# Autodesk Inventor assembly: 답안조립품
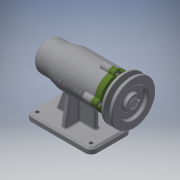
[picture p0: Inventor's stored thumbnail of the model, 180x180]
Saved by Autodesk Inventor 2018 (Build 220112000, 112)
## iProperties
Created: 2019-07
Part Number: 답안조립품
Material: 일반
Document SubType Name: Assembly
Designer: USER
Author: USER
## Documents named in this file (12)
- C:\Users\USER\Desktop\490704V1049\답안조립품.iam
- C:\Users\USER\Desktop\490704V1049\본체.ipt
- C:\Users\USER\Desktop\490704V1049\V벨트풀리.ipt
- C:\Users\USER\Desktop\490704V1049\멈춤나사 M3.ipt
- C:\Users\USER\Desktop\490704V1049\베어링 6004.ipt
- C:\Users\USER\Desktop\490704V1049\베어링 51202.ipt
- C:\Users\USER\Desktop\490704V1049\볼트 M4.ipt
- C:\Users\USER\Desktop\490704V1049\어댑터슬리브.ipt
- C:\Users\USER\Desktop\490704V1049\오일 실.ipt
- C:\Users\USER\Desktop\490704V1049\축.ipt
- C:\Users\USER\Desktop\490704V1049\커버.ipt
- C:\Users\USER\Desktop\490704V1049\키 5 x 5 x 16.ipt
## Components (1 placed, 1 different names)
1. V벨트풀리:1
